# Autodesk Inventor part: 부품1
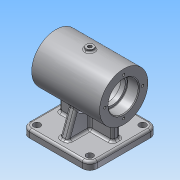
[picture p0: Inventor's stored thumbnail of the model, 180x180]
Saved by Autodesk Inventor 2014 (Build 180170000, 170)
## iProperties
Created: 2019-06
Part Number: 부품1
Material: 알루미늄 6061
Document SubType Name: Modeling
Designer: NET
Density: 2.71 g/cm^3
Appearance: 알루미늄 - 평지
Mass: 612.954 g
Surface Area: 624.62 cm^2
Volume: 226.182 cm^3
Author: NET
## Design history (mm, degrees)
sketch "스케치1"
  geometry: L1 (45, 0)-(-45, 0); L2 (-45, 0)-(-45, 32); L3 (-45, 32)-(45, 32); L4 (45, 32)-(45, 0); L5 (45, 20)-(30.6, 20); L6 (30, 19.4)-(30, 17); L7 (30, 17)-(24, 17); L8 (24, 17)-(24, 22); L9 (21, 25)-(-21, 25); L10 (-24, 22)-(-24, 17); L11 (-24, 17)-(-30, 17); L12 (-30, 17)-(-30, 19.4); L13 (-30.6, 20)-(-45, 20); A1 r 0.6 centre (-30.6, 19.4) between (-30, 19.4) and (-30.6, 20); A2 r 3 centre (21, 22) between (24, 22) and (21, 25); A3 r 3 centre (-21, 22) between (-21, 25) and (-24, 22); A4 r 0.6 centre (30.6, 19.4) between (30.6, 20) and (30, 19.4); 6 further points
  constraints: 26 end point, 10 point on line, 8 point on circle, 8 tangent, 7 parallel, 4 centre point, 4 perpendicular, 2 coincident, 1 collinear, 1 equal radius, 1 horizontal, 1 midpoint
  dimensions: "d0" = 90 distance of L1.start L1.end; "d1" = 64 diameter of L3 L1; "d2" = 40 diameter of L5 L1; "d3" = 34 diameter of L7 L1; "d4" = 50 diameter of L9 L1; "d5" = 34 diameter of L11 L1; "d6" = 40 diameter of L13 L1; "d7" = 15 distance of L5.start point (30, 20); "d8" = 48 distance of point (24, 25) point (-24, 25); "d9" = 6 distance of L6.end L7.end; "d10" = 15 distance of point (-30, 20) L13.end; "d11" = 0.6 radius of A1; "d12" = 3 radius of A2; "d162" = 0.6 radius of A4
revolve "회전1" sketch "스케치1" stored, may be unused: angle "d13" = 90 deg
node "작업 평면1"
sketch "스케치5"
  geometry: L1 (-45, -45)-(45, -45); L2 (45, -45)-(45, 45); L3 (45, 45)-(-45, 45); L4 (-45, 45)-(-45, -45); L5 (-45, -45)-(45, 45); L6 (45, -45)-(-45, 45); 1 further point
  constraints: 12 end point, 2 midpoint, 2 parallel, 1 horizontal, 1 perpendicular
  dimensions: "d45" = 90 distance of L2.end L3.end; "d46" = 90 distance of L1.end L2.end
extrude "돌출2" join sketch "스케치5" distance "d47" = 10; taper "d48" = 0 deg
node "작업 평면2"
sketch "스케치7"
  geometry: C1 r 5 at (0, 0); 1 further point
  constraints: 1 centre point, 1 coincident
  dimensions: "d59" = 10 diameter of C1
extrude "돌출3" join sketch "스케치7" distance "d60" = 10; taper "d61" = 0 deg
sketch "스케치8"
  geometry: C1 r 5 at (0, 0) reference; 1 further point
  constraints: 1 coincident
hole "구멍1" sketch "스케치8" at (0, 0) diameter "d62" = 4.917; stored, may be unused: countersink angle "d66" = 90 deg, drill point angle "d68" = 118 deg; dims "d63" = 6, "d64" = 4, "d65" = 2, "d67" = 15
sketch "스케치12"
  geometry: C1 r 20 at (0, 0) reference; 1 further point
  constraints: 1 horizontal alignment
  dimensions: "d79" = 25 distance of C1.centre point (-25, 0)
hole "구멍2" sketch "스케치12" at (-25, 0) diameter "d80" = 3.242; stored, may be unused: countersink angle "d84" = 90 deg, drill point angle "d86" = 118 deg; dims "d81" = 7, "d82" = 4, "d83" = 2, "d85" = 9
sketch "스케치13"
  geometry: L1 (-23.058, -22.189)-(-35, -55); L2 (45, -55)-(-45, -55) reference; L3 (23.058, -22.189)-(35, -55); A1 r 32 centre (0, 0) between (-23.058, -22.189) and (23.058, -22.189) reference; 1 further point
  constraints: 4 end point, 2 point on circle, 2 point on line
  dimensions: "d90" = 110 deg angle of L2 L3; "d91" = 110 deg angle of L2 L1; "d92" = 10 distance of L1.end L2.end; "d93" = 10 distance of L3.end L2.start
extrude "돌출4" join sketch "스케치13" stored distance "d94" = 10; taper "d95" = 0 deg
sketch "스케치14"
  geometry: L1 (45, -45)-(45, 45) reference; L2 (-35, -5)-(35, -5); L3 (35, -5)-(35, 5); L4 (35, 5)-(-35, 5); L5 (-35, 5)-(-35, -5); L6 (-35, -5)-(35, 5); L7 (35, -5)-(-35, 5); 1 further point
  constraints: 12 end point, 2 midpoint, 2 parallel, 1 horizontal, 1 perpendicular
  dimensions: "d96" = 10 distance of L2.end L3.end; "d97" = 10 distance between parallel lines of L1 L3
extrude "돌출5" join sketch "스케치14" stored distance "d98" = 10; taper "d99" = 0 deg
fillet "모깎기1" dims "d100" = 3
fillet "모깎기2" dims "d101" = 3
fillet "모깎기3" dims "d102" = 10
fillet "모깎기4" dims "d103" = 3
sketch "스케치15"
  geometry: C1 r 4.5 at (-35, 35); C2 r 4.5 at (35, 35); C3 r 4.5 at (35, -35); C4 r 4.5 at (-35, -35); A1 r 7 centre (-35, -35) between (-42, -35) and (-35, -42) reference; A2 r 7 centre (35, -35) between (35, -42) and (42, -35) reference; A3 r 7 centre (35, 35) between (42, 35) and (35, 42) reference; A4 r 7 centre (-35, 35) between (-35, 42) and (-42, 35) reference; 1 further point
  constraints: 4 centre point, 4 coincident
  dimensions: "d104" = 9 diameter of C1; "d105" = 9 diameter of C2; "d106" = 9 diameter of C3; "d107" = 9 diameter of C4
extrude "돌출6" cut sketch "스케치15" distance "d108" = 10; taper "d109" = 0 deg
sketch "스케치16"
  geometry: L1 (-25, 40)-(-25, 25); L2 (-21, -25)-(-21, 25) reference; L3 (-25, 25)-(-40, 25); L4 (-40, 25)-(-40, -25); L5 (-40, -25)-(-25, -25); L6 (-25, -25)-(-25, -40); L7 (-25, -40)-(25, -40); L8 (25, -40)-(25, -25); L9 (25, -25)-(40, -25); L10 (40, -25)-(40, 25); L11 (40, 25)-(25, 25); L12 (25, 25)-(25, 40); L13 (25, 40)-(-25, 40); L14 (35, 42)-(-35, 42) reference; L15 (-45, -35)-(-45, 35) reference; L16 (-35, 45)-(35, 45) reference; L17 (45, 35)-(45, -35) reference; L18 (35, -45)-(-35, -45) reference; C1 r 4.5 at (-35, -35) reference; C2 r 4.5 at (35, 35) reference; C3 r 4.5 at (-35, 35) reference; C4 r 4.5 at (35, -35) reference; C5 r 10 at (35, 35); C6 r 10 at (35, -35); C7 r 10 at (-35, -35); C8 r 10 at (-35, 35); A1 r 10 centre (-35, -35) between (-45, -35) and (-35, -45) reference; A2 r 10 centre (-35, 35) between (-35, 45) and (-45, 35) reference; A3 r 10 centre (35, 35) between (45, 35) and (35, 45) reference; A4 r 10 centre (35, -35) between (35, -45) and (45, -35) reference; 1 further point
  constraints: 24 end point, 8 parallel, 8 tangent, 4 centre point, 4 coincident, 2 collinear, 2 perpendicular
  dimensions: "d141" = 80 distance between parallel lines of L7 L13; "d142" = 80 distance between parallel lines of L4 L10; "d143" = 40 distance from line of point (0, 0) L4; "d144" = 40 distance from line of point (0, 0) L13; "d145" = 20 diameter of C5; "d146" = 20 diameter of C6; "d147" = 20 diameter of C7; "d148" = 20 diameter of C8
extrude "돌출8" cut sketch "스케치16" distance "d149" = 5; taper "d150" = 0 deg
fillet "모깎기6" dims "d151" = 10
fillet "모깎기7" dims "d152" = 3
fillet "모깎기8" dims "d153" = 3
fillet "모깎기9" dims "d154" = 3
sketch "스케치17"
  geometry: L1 (70, 0)-(0, 0) reference; L2 (80, -7)-(80, 0) reference; 2 further points
  constraints: 1 other
  dimensions: "d155" = 45 distance from line of point (35, -4) L2; "d156" = 4 distance from line of L1 point (35, -4)
feature "엠보싱1" sketch "스케치17" dims "d13" = 90 deg, "d157" = 0.5, "d158" = 0
chamfer "모따기1" distance "d159" = 1; stored, may be unused: second distance "d160" = 2, angle "d161" = 45 deg
fillet "모깎기10" dims "d163" = 2
node "솔리드1"
pattern_circular "원형 패턴1" dims angle "d88" = 360 deg
mirror "대칭1"
node "절단 모서리 투영1"
other parameters: "d14" = -65, "d58" = 35
